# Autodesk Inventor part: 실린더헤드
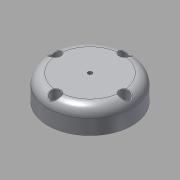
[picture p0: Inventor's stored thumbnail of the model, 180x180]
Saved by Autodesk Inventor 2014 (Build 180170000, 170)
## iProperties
Created: 2016-11
Part Number: 실린더헤드
Material: 알루미늄 6061
Document SubType Name: Modeling
Designer: mduedu
Density: 2.71 g/cm^3
Appearance: 알루미늄 - 평지
Mass: 284.829 g
Surface Area: 227.25 cm^2
Volume: 105.103 cm^3
Author: mduedu
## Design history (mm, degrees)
sketch "스케치1"
  geometry: C1 r 42.5 at (0, 0); 1 further point
  constraints: 1 centre point, 1 coincident
  dimensions: "d0" = 85 diameter of C1
extrude "돌출1" new body sketch "스케치1" distance "d1" = 25; taper "d2" = 0 deg
fillet "모깎기1" dims "d3" = 10
sketch "스케치2"
  geometry: C1 r 30 at (0, 0); 1 further point
  constraints: 1 centre point, 1 coincident
  dimensions: "d4" = 60 diameter of C1
extrude "돌출2" join sketch "스케치2" distance "d5" = 5; taper "d6" = 0 deg
sketch "스케치3"
  geometry: C1 r 25 at (0, 0); 1 further point
  constraints: 1 centre point, 1 coincident
  dimensions: "d7" = 50 diameter of C1
extrude "돌출3" cut sketch "스케치3" distance "d8" = 20; taper "d9" = 0 deg
hole "구멍1" diameter "d12" = 4.134; stored, may be unused: countersink angle "d16" = 90 deg, drill point angle "d18" = 118 deg; dims "d10" = 10, "d11" = 10, "d13" = 6, "d14" = 4, "d15" = 2, "d17" = 8
chamfer "모따기1" distance "d19" = 1; stored, may be unused: second distance "d20" = 2, angle "d21" = 45 deg
fillet "모깎기2" dims "d22" = 3
sketch "스케치4"
  geometry: C1 r 17.5 at (0, 0); 1 further point
  constraints: 1 centre point, 1 coincident
  dimensions: "d23" = 35 diameter of C1
extrude "돌출4" cut sketch "스케치4" distance "d24" = 2; taper "d25" = 0 deg
fillet "모깎기3" dims "d26" = 0.5
sketch "스케치5" dims "d32" = 70
  geometry: C1 r 5 at (0, 35); 3 further points
  constraints: 2 coincident, 2 vertical alignment, 1 centre point, 2 other
  dimensions: "d33" = 10 diameter of C1
extrude "돌출5" cut sketch "스케치5" distance "d34" = 10; taper "d35" = 0 deg
sketch "스케치6" dims "d39" = 70
  geometry: 6 further points
  constraints: 2 vertical alignment, 1 coincident, 7 other
  dimensions: "d42" = 360 deg dimension on point (0, -35) point (0, 0) (derived)
sketch "스케치7"
  geometry: 4 further points
  constraints: 4 other
hole "구멍2" sketch "스케치7" at (0, 70), (-35, 35), (35, 35), (0, 0) diameter "d44" = 5.5; stored, may be unused: countersink angle "d48" = 90 deg, drill point angle "d50" = 0 deg; dims "d45" = 6, "d46" = 4, "d47" = 2, "d49" = 8
fillet "모깎기4" dims "d51" = 0.5
node "솔리드1"
pattern_circular "원형 패턴1" dims angle "d37" = 360 deg
